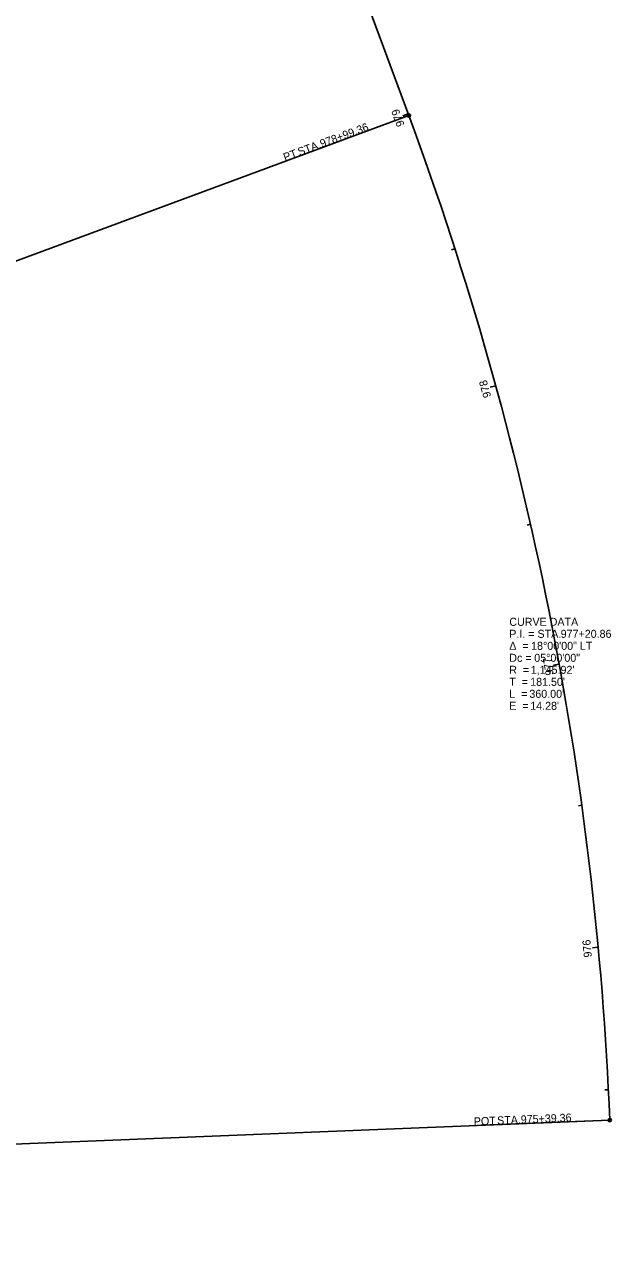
# Model space of a CAD drawing. Extents: x 2227316 to 2230534, y 679272 to 682221.
# Drawn here: x 2228256.1 to 2228461.6, y 679271.7 to 679701.5 of the extents above; entities that cross this region are included whole.
import ezdxf

# ---------------------------------------------------------------- set-up
doc = ezdxf.new("R2010")
doc.units = 0
for name, color, linetype in [('GE_X_Alignment', 7, 'Continuous'), ('GE_X_Alignment_100_Cardinal_Points', 7, 'Continuous'), ('GE_X_Alignment_100_Curve_Data', 7, 'Continuous'), ('GE_X_Alignment_100_Stations', 7, 'Continuous'), ('SC_Scratch1', 7, 'Continuous'), ('SC_Scratch2', 7, 'Continuous')]:
    doc.layers.add(name, color=color, linetype=linetype)

msp = doc.modelspace()

# ---------------------------------------------------------------- linework, layer by layer
at = {"layer": 'GE_X_Alignment'}
msp.add_line((2228390.69, 679669.61), (2228340.08, 679806.29), dxfattribs=at)
msp.add_arc((2227316.07, 679271.72), 1145.92, 2.31734, 20.31734, dxfattribs=at)
at = {"layer": 'GE_X_Alignment_100_Cardinal_Points'}
for p, q in [((2228390.69, 679669.61), (2228348.49, 679653.98)), ((2228461.05, 679318.06), (2228416.08, 679316.24))]:
    msp.add_line(p, q, dxfattribs=at)
for centre in [(2228390.69, 679669.61), (2228461.05, 679318.06)]:
    msp.add_circle(centre, 0.6, dxfattribs=at)
at = {"layer": 'GE_X_Alignment_100_Stations'}
for p, q in [((2228390.47, 679670.21), (2228388.59, 679669.51)), ((2228406.83, 679622.97), (2228405.68, 679622.6)), ((2228421.11, 679575.05), (2228419.18, 679574.52)), ((2228433.29, 679526.56), (2228432.12, 679526.3)), ((2228443.34, 679477.59), (2228441.37, 679477.23)), ((2228451.25, 679428.22), (2228450.06, 679428.06)), ((2228456.99, 679378.56), (2228455, 679378.37)), ((2228460.57, 679328.69), (2228459.37, 679328.63))]:
    msp.add_line(p, q, dxfattribs=at)
at = {"layer": 'SC_Scratch1'}
msp.add_line((2228390.69, 679669.61), (2228340.08, 679806.29), dxfattribs=at)
msp.add_arc((2227316.07, 679271.72), 1145.92, 2.31734, 20.31734, dxfattribs=at)
at = {"layer": 'SC_Scratch2'}
for q in [(2228390.69, 679669.61), (2228461.05, 679318.06)]:
    msp.add_line((2227316.07, 679271.72), q, dxfattribs=at)

# ---------------------------------------------------------------- texts
at = {"layer": 'GE_X_Alignment_100_Cardinal_Points'}
for s, rotation, p in [('978+99.36', 20.3173, (2228360.18, 679658.35)), (' STA. ', 20.3173, (2228351.43, 679655.11)), ('PT', 20.3173, (2228347.35, 679653.6)), ('975+39.36', 2.3173, (2228429.94, 679316.84)), ('POT', 2.3173, (2228413.5, 679316.17)), (' STA. ', 2.3173, (2228420.62, 679316.46))]:
    msp.add_text(s, height=2.8, rotation=rotation, dxfattribs=at).set_placement(p)
at = {"layer": 'GE_X_Alignment_100_Curve_Data'}
for s, p in [('CURVE DATA', (2228425.87, 679491.03)), ('P.I. = STA. ', (2228425.87, 679486.83)), ('977+20.86', (2228443.86, 679486.83)), ('Δ  = ', (2228425.87, 679482.63)), ('18°00\'00" LT', (2228433.51, 679482.63)), ('Dc = ', (2228425.87, 679478.43)), ('05°00\'00"', (2228434.61, 679478.43)), ('R  = ', (2228425.87, 679474.23)), ("1,145.92'", (2228433.4, 679474.23)), ('T  = ', (2228425.87, 679470.03)), ("181.50'", (2228433.19, 679470.03)), ('L  = ', (2228425.87, 679465.83)), ("360.00'", (2228432.9, 679465.83)), ('E  = ', (2228425.87, 679461.63)), ("14.28'", (2228433.21, 679461.63))]:
    msp.add_text(s, height=2.8, dxfattribs=at).set_placement(p)
at = {"layer": 'GE_X_Alignment_100_Stations'}
for s, rotation, p in [('979', 110.3173, (2228389.24, 679666.32)), ('978', 105.3493, (2228419.56, 679571.26)), ('977', 100.3493, (2228441.46, 679473.95)), ('976', 95.3493, (2228454.81, 679375.08))]:
    msp.add_text(s, height=2.8, rotation=rotation, dxfattribs=at).set_placement(p)

doc.saveas('drawing.dxf')
